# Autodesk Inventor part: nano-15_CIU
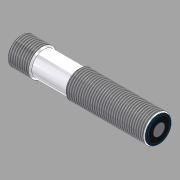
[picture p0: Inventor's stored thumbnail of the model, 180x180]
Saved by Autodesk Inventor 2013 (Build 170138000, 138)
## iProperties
Shininess: 20.0
Length Units: 11269
Angle Units: 11279
Time Units: 11290
Mass Units: 11283
Length Display Precision: 2
Angle Display Precision: 2
Part Number: nano-15_CIU
Material: Nichtrostender Stahl - 440C
Document SubType Name: Modellieren
Description: Ipc-25 /CXX/M18
Checked By: Alves
Created: 2005-08
Designer: Ohle
Manufacturer: Standard
Standards Organization: Custom
Density: 0.0
Volumn: 0.0
Area: 0.0
PropertySet Name: Model Information
Control State: 0
Master: False
Checked Out: False
BESTELLNUMMER: Ipc-25 /CXX/M18
ME: ST
Title: Ipc Sensoren
Author: Ohle
Comments: keine Bemerkung
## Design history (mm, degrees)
sketch "Skizze10"
  geometry: L1 (-42.478, 0)-(9.622, 0); L2 (-45.9, 8)-(-45.9, 8); L3 (-24.778, 6)-(8.722, 6); L4 (9.612, 4.75)-(9.612, 2.5); L5 (9.612, 2.5)-(9.622, 2.5); L6 (9.622, 2.5)-(9.622, 0); L7 (9.622, 0)-(-82, 0); L8 (1.522, 8.25)-(1.522, 8.25); L9 (-25.478, 5.3)-(-24.778, 6); L10 (9.122, 5.6)-(8.722, 6); L11 (-49.978, 6)-(-41.178, 6); L12 (-40.478, 5.3)-(-25.478, 5.3); L13 (-50.478, 4.5)-(-42.478, 4.5); L14 (-42.478, 0)-(-42.478, 4.5); L15 (9.122, 5.6)-(9.322, 5.6); L16 (-50.478, 5.5)-(-50.478, 4.5); L17 (-50.478, 5.5)-(-49.978, 6); L18 (9.622, 5.3)-(9.622, 4.75); L19 (9.622, 4.75)-(9.612, 4.75); L20 (-41.178, 6)-(-40.478, 5.3); A1 r 0.3 centre (9.322, 5.3) between (9.622, 5.3) and (9.322, 5.6); 3 further points
  constraints: 40 end point, 5 point on line, 3 perpendicular, 2 horizontal, 2 parallel, 2 point on circle, 1 centre point, 1 collinear, 1 tangent
  dimensions: "d136" = 2.5 distance of L5.end L1.end; "d138" = 6 distance between parallel lines of L3 L7; "d171" = 4.5 distance between parallel lines of L13 L1; "d256" = 45 deg angle of L3 L9; "d269" = 6 distance between parallel lines of L7 L11; "d289" = 135 deg angle of L10 L3; "d293" = 0.5 horizontal distance of L16.start L11.start; "d294" = 45 deg angle of L17 L11 (derived); "d295" = 8 distance of L13.start L13.end; "d331" = 0.01 distance between parallel lines of L4 L6; "d335" = 0.3 radius of A1; "d338" = 0.01 distance between parallel lines of L18 L4; "d339" = 4.75 distance between parallel lines of L7 L19; "d340" = 5.3 distance between parallel lines of L1 L12; "d341" = 10 distance from line of L12.start L16; "d343" = 135 deg angle of L20 L11; "d347" = 0.2 distance of L10.start L15.end; "d348" = 25 distance from line of L9.start L16; "d349" = 59.6 distance from line of L10.start L16; "d350" = 5.6 distance between parallel lines of L15 L7
revolve "Grundkörper pico+" sketch "Skizze10" stored, may be unused: angle "d168" = 90 deg
sketch "Skizze13"
  geometry: L1 (-3.409, -3.409)-(3.61, 3.61); L2 (-3.439, 3.439)-(4.105, -4.105); L3 (-8.4, 0)-(8.4, 0) reference; C1 r 0.5 at (2.121, -2.121); C2 r 0.5 at (2.121, 2.121); C3 r 0.5 at (-2.121, 2.121); C4 r 0.5 at (-2.121, -2.121); C5 r 4.5 at (0, 0) reference; C6 r 0.5 at (0, 0); A1 r 3 centre (0, 0) between (-2.121, 2.121) and (2.121, 2.121); 2 further points
  constraints: 6 centre point, 6 point on line, 4 coincident, 4 end point, 4 equal radius, 4 point on circle, 1 horizontal alignment, 1 perpendicular
  dimensions: "d208" = 1 diameter of C3; "d209" = 6 diameter of A1
extrude "Pole" join sketch "Skizze13" distance "d212" = 7; taper "d213" = 0 deg
fillet "Rundung Pole" dims "d214" = 0.5
sketch "Skizze14"
  geometry: C1 r 0.5 at (0, -4.5); A1 r 4.5 centre (0, 0) between (4.435, -0.762) and (4.435, 0.762); A2 r 4.5 centre (0, 0) between (0, 4.5) and (0.499, 4.472) reference; A3 r 0.5 centre (0, 4.5) between (-0.499, 4.472) and (0.499, 4.472); 3 further points
  constraints: 9 point on circle, 3 centre point, 3 coincident, 1 horizontal alignment, 1 vertical alignment
  dimensions: "d215" = 9 diameter of A1; "d280" = 1 diameter of A3; "d330" = 1 diameter of C1
extrude "Verdrehsicherung" join sketch "Skizze14" distance "d217" = 7.9; taper "d218" = 0 deg
feature "Gewinde7" dims "d351" = 10, "d352" = 0
feature "Gewinde8" dims "d353" = 10, "d354" = 0
node "Volumenkörper1"
node "Volumenkörper"
node "Oberflächenkörper"
other parameters: "d10" = 14, "d130" = 0.2
